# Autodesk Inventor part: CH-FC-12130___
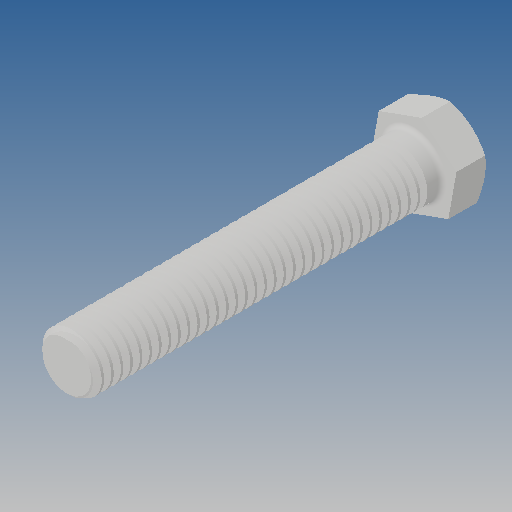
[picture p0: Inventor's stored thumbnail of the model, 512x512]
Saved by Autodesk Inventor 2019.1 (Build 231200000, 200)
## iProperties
Created: 2010-06
Part Number: CH-FC-12130___
Material: Ogólny
Document SubType Name: Modeling
Designer: CADENGINEERING4
Density: 1 g/cm^3
Appearance: Domyślna
Author: CADENGINEERING4
Revision Number: ANY
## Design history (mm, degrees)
feature "NONE"
node "Bryła1"
